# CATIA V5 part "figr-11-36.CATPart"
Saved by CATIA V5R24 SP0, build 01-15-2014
Part number: Part1
Bounding box of the stored display mesh (mm): x -55 to 66, y -170 to 170, z -50 to 0
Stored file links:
  D:\KAVITA\CATIA V5-6R2014 Project_ Kavita\CATIA V5-6R2014_partfiles\Partfiles\c11_catia_v5-6r2014_prt\figr-11-36.CATPart
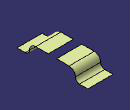
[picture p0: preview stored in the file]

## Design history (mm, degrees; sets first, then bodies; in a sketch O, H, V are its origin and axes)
Set1
  Extrude1: Element1 Sketch1, Lim1 66, Lim2 55, Direction yz-plane
  Symmetry1: ToTransfor Extrude1, Reference zx-plane
Body1 (main body)
  Sketch1 on yz-plane, origin (0, 0, 0), H (0, 1, 0), V (0, 0, 1)
    point P1 (20, 0)
    line L1 (20, 0) -> (80, 0)
    arc A1 centre (80, -30) radius 30 from (80, 0) to (110, -30) cw
    arc A2 centre (130, -30) radius 20 from (110, -30) to (130, -50) ccw
    line L2 (130, -50) -> (170, -50)
    coincidence: P1 H
    horizontal: L1 H
    tangency: A1 L1, A2 A1, L2 A2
